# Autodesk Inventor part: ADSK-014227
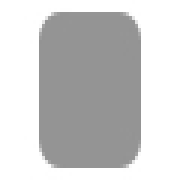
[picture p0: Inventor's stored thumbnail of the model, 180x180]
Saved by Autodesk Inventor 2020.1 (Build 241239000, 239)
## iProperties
Created: 2019-01
Part Number: ADSK-014227
Material: Stahl, weich
Document SubType Name: Modeling
Designer: lutzd
Language: de-DE
Size Designation: 5 x 39,384472 x 39,384472
Categories: <MemberInstance><Categories><Category DisplayName="Sonstige Bauteile" InternalName="5aa15e00-363f-49f2-933f-16f664388e3f" Mnemonic="OTHER"><Category DisplayName
Mass: 60.0398 g
Surface Area: 38.0412 cm^2
Volume: 7.64838 cm^3
Density: 7.85 g/cm^3
Appearance: Halbpoliert
Dimensions: 39,4x39,4x5 mm
Mass: 0,06 kg
DocNumber: ADSK-014227
Folder: 01 - Themengebiete\Simplification\01 - Packaging machine\ADSK-014200\Frame\
VDS_Category: 3D Komponenten
VDS_NumSchm: Autodesk
IsCustomPart: 1
Title: Endcap
Author: lutzd
Revision Number: -
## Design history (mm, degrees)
sketch "Sketch1"
  geometry: L1 (0, 20.175)-(0, -21.446); L2 (-20.203, 0)-(20.169, 0); L3 (-19.692, 19.692)-(19.692, 19.692); L4 (19.692, 19.692)-(19.692, -19.692); L5 (19.692, -19.692)-(-19.692, -19.692); L6 (-19.692, -19.692)-(-19.692, 19.692); 1 further point
  constraints: 12 end point, 2 horizontal, 2 parallel, 2 point on line, 1 perpendicular, 1 vertical
  dimensions: "d0" = 39.38447 distance between parallel lines of L5 L3 (= height); "d1" = 19.69224 distance between parallel lines of L2 L3 (= 0.5 x height); "d2" = 39.38447 distance between parallel lines of L6 L4 (= width); "d3" = 19.69224 distance between parallel lines of L6 L1 (= 0.5 x width)
extrude "Extrusion1" new body sketch "Sketch1" distance "d4" = 5 (= thickness); taper "d5" = 0 deg
fillet "Fillet1" dims "d6" = 5 (= fillet), "d7" = 0, "fillet" = 5 [user parameter; used in 1 equation term]
chamfer "Chamfer1" distance "d8" = 0 (computed from chamfer); stored, may be unused: second distance "d9" = 2, angle "d10" = 45 deg; dims "d11" = 0, "chamfer" = 0 [user parameter; used in 1 equation term]
body "Solid1"
other parameters: "thickness" = 5 [user parameter; used in 1 equation term], "width" = 39.38447 [user parameter; used in 2 equation terms], "height" = 39.38447 [user parameter; used in 2 equation terms]
